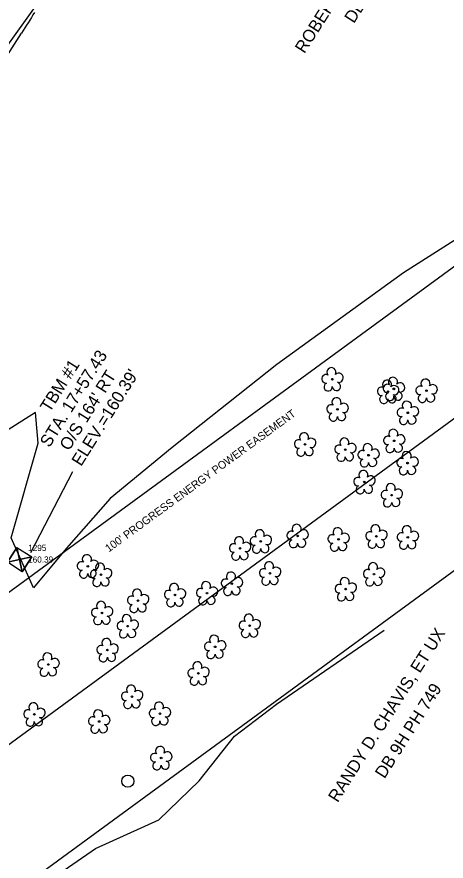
# Model space of a CAD drawing. Extents: x 1840200 to 1849051, y 348278 to 353012.
# Drawn here: x 1844872.5 to 1845047.4, y 350604.9 to 350948.7 of the extents above; entities that cross this region are included whole.
import ezdxf

# ---------------------------------------------------------------- set-up
doc = ezdxf.new("R2010")
doc.units = 0
for name, color, linetype in [('CTL Bench Mark CELL', 7, 'Continuous'), ('CTL Bench Mark Cogo Elevation', 7, 'Continuous'), ('CTL Bench Mark Cogo Number', 7, 'Continuous'), ('CTL Bench Mark Leader', 7, 'Continuous'), ('CTL Bench Mark Text', 7, 'Continuous'), ('Default', 7, 'Continuous'), ('Exist Property Deed Book Text', 7, 'Continuous'), ('Exist Property Line', 7, 'Continuous'), ('Exist Property Owner Text', 7, 'Continuous'), ('Exist Right of Way Easement Line', 7, 'Continuous'), ('Exist Right of Way Easement Line Text', 7, 'Continuous'), ('Exist Right of Way Line', 7, 'Continuous'), ('Exist Utilities Other Pole CELL', 7, 'Continuous'), ('Exist Vegetation Tree CELL', 7, 'Continuous'), ('Exist Vegetation Woods Line', 7, 'Continuous')]:
    doc.layers.add(name, color=color, linetype=linetype)

# ---------------------------------------------------------------- blocks, each defined once
blk = doc.blocks.new('CTL BENCH MARK')
at = {"layer": 'CTL Bench Mark CELL'}
blk.add_line((0, 0), (0, 0), dxfattribs=at)
blk.add_lwpolyline([(-0.072, 0.07175), (0.07175, 0.07175), (0.07175, -0.072), (-0.072, -0.072)], close=True, dxfattribs=at)
for points in [[(0.07175, 0.07175), (-0.072, -0.072), (-0.000125, -0.000125), (0.07175, -0.072), (-0.072, 0.07175)], [(-0.000125, -0.000125), (0.07175, 0.07175), (-0.072, 0.07175), (-0.000125, -0.000125)], [(-0.000125, -0.000125), (-0.072, -0.072), (0.07175, -0.072), (-0.000125, -0.000125)]]:
    blk.add_lwpolyline(points, dxfattribs=at)
blk = doc.blocks.new('EXIST UTILITIES OTHER POLE')
at = {"layer": 'Exist Utilities Other Pole CELL'}
blk.add_circle((0, 0), 0.0493, dxfattribs=at)
blk = doc.blocks.new('EXIST VEGETATION TREE')
at = {"layer": 'Exist Vegetation Tree CELL'}
blk.add_line((0, 0), (0, 0), dxfattribs=at)
blk.add_circle((0, 0), 0.00652, dxfattribs=at)
for centre, radius, start, end in [((-0.0077, 0.0575), 0.0371, 330.16508, 219.71335), ((-0.0521, 0.0031), 0.0345, 62.66361, 279.3457), ((0.051, 0.0118), 0.038, 257.1011, 134.19993), ((-0.0341, -0.0624), 0.0338, 111.56708, 6.23104), ((0.0335, -0.058), 0.034, 181.28216, 74.55999)]:
    blk.add_arc(centre, radius, start, end, dxfattribs=at)

msp = doc.modelspace()

# ---------------------------------------------------------------- linework, layer by layer
at = {"layer": 'CTL Bench Mark Leader'}
msp.add_lwpolyline([(1844878.28, 350730.61), (1844895.39, 350763.57)], dxfattribs=at)
at = {"layer": 'Exist Property Line'}
msp.add_line((1844729.25, 350550.14), (1845268.47, 350944.43), dxfattribs=at)
at = {"layer": 'Exist Right of Way Easement Line'}
for p, q in [((1844606.92, 350522.63), (1845238.95, 350984.79)), ((1844458.92, 350290.53), (1845297.98, 350904.07))]:
    msp.add_line(p, q, dxfattribs=at)
at = {"layer": 'Exist Right of Way Line'}
msp.add_line((1844461.07, 350293.9), (1844874.4, 350942.13), dxfattribs=at)
msp.add_arc((1849048.13, 348280.84), 4950, 147.36144, 147.47735, dxfattribs=at)
at = {"layer": 'Exist Vegetation Woods Line'}
for points in [[(1844796.9, 350805.6), (1844816.79, 350855.86), (1844851.04, 350912.56), (1844897.15, 350976.91), (1844931.29, 351031.99), (1844954.04, 351069.23), (1844985.12, 351120.08), (1845035.99, 351203.55)], [(1845070.01, 350869.81), (1845030.11, 350844.53), (1844978.5, 350807.17), (1844935.82, 350773.29), (1844910.5, 350752.55), (1844892.75, 350732.3), (1844879.25, 350716.15), (1844870.18, 350736.58), (1844881.18, 350775.09), (1844880.17, 350787.58), (1844859.57, 350774.67), (1844839.4, 350706.41), (1844822.64, 350670.45), (1844807.74, 350646.85), (1844790.3, 350647.95), (1844792.72, 350669.3), (1844820.73, 350703.89), (1844816.98, 350750.84), (1844800.41, 350764.51), (1844788.23, 350770.16), (1844784.85, 350775.08), (1844788.4, 350786.96), (1844796.9, 350805.6)], [(1844820.52, 350547.53), (1844856.07, 350576.6), (1844904.56, 350610.06), (1844930.4, 350621.75), (1844946.86, 350637.64), (1844961.25, 350655.71), (1844978.34, 350668.76), (1845022.23, 350698.9)]]:
    msp.add_lwpolyline(points, dxfattribs=at)

# ---------------------------------------------------------------- block references
at = {"layer": 'CTL Bench Mark CELL', "xscale": 49.99999999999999, "yscale": 50, "rotation": 57.56724915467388}
msp.add_blockref('CTL BENCH MARK', (1844873.63, 350727.7), dxfattribs=at)
at = {"layer": 'Default', "xscale": 50, "yscale": 50}
for name, p in [('EXIST VEGETATION TREE', (1845001.08, 350801.15)), ('EXIST VEGETATION TREE', (1845023.74, 350796.09)), ('EXIST VEGETATION TREE', (1845026.14, 350797.21)), ('EXIST VEGETATION TREE', (1845039.43, 350796.45)), ('EXIST VEGETATION TREE', (1845003.16, 350788.87)), ('EXIST VEGETATION TREE', (1845031.83, 350787.48)), ('EXIST VEGETATION TREE', (1845026.29, 350776.05)), ('EXIST VEGETATION TREE', (1844989.94, 350774.62)), ('EXIST VEGETATION TREE', (1845006.36, 350772.5)), ('EXIST VEGETATION TREE', (1845015.83, 350770.2)), ('EXIST VEGETATION TREE', (1845031.72, 350766.98)), ('EXIST VEGETATION TREE', (1845014.11, 350759.31)), ('EXIST VEGETATION TREE', (1845025.28, 350753.94)), ('EXIST VEGETATION TREE', (1844986.91, 350737.34)), ('EXIST VEGETATION TREE', (1844971.9, 350735.1)), ('EXIST VEGETATION TREE', (1845003.6, 350735.95)), ('EXIST VEGETATION TREE', (1845019.01, 350737.16)), ('EXIST VEGETATION TREE', (1845031.81, 350736.72)), ('EXIST VEGETATION TREE', (1844963.44, 350732.24)), ('EXIST VEGETATION TREE', (1844901.45, 350724.94)), ('EXIST VEGETATION TREE', (1844906.82, 350721.53)), ('EXIST VEGETATION TREE', (1844975.67, 350722.1)), ('EXIST VEGETATION TREE', (1845018.02, 350721.74)), ('EXIST VEGETATION TREE', (1844960.13, 350717.9)), ('EXIST VEGETATION TREE', (1844936.94, 350713.27)), ('EXIST VEGETATION TREE', (1844950, 350714.02)), ('EXIST VEGETATION TREE', (1845006.51, 350715.66)), ('EXIST VEGETATION TREE', (1844921.91, 350710.96)), ('EXIST VEGETATION TREE', (1844907.22, 350705.97)), ('EXIST VEGETATION TREE', (1844917.69, 350700.57)), ('EXIST VEGETATION TREE', (1844967.38, 350700.74)), ('EXIST VEGETATION TREE', (1844909.43, 350690.84)), ('EXIST VEGETATION TREE', (1844953.31, 350692.16)), ('EXIST VEGETATION TREE', (1844885.4, 350684.97)), ('EXIST VEGETATION TREE', (1844946.51, 350681.34)), ('EXIST VEGETATION TREE', (1844919.44, 350671.85)), ('EXIST VEGETATION TREE', (1844879.67, 350664.64)), ('EXIST VEGETATION TREE', (1844906.06, 350661.75)), ('EXIST VEGETATION TREE', (1844930.82, 350664.92)), ('EXIST VEGETATION TREE', (1844931.31, 350646.9)), ('EXIST UTILITIES OTHER POLE', (1844917.75, 350637.45))]:
    msp.add_blockref(name, p, dxfattribs=at)

# ---------------------------------------------------------------- texts
at = {"layer": 'CTL Bench Mark Cogo Elevation'}
msp.add_text('160.39', height=2.5, dxfattribs=at).set_placement((1844877.13, 350726.45))
at = {"layer": 'CTL Bench Mark Cogo Number'}
msp.add_text('1295', height=2.5, dxfattribs=at).set_placement((1844877.13, 350731.2))
at = {"layer": 'CTL Bench Mark Text'}
for s, p in [('STA. 17+57.43', (1844885.8, 350773.03)), ('TBM #1', (1844885.91, 350787.33)), ("O/S 164' RT", (1844893.8, 350771.69)), ("ELEV.=160.39'", (1844898.72, 350765.4))]:
    msp.add_text(s, height=5, rotation=57.9144, dxfattribs=at).set_placement(p)
at = {"layer": 'Exist Property Deed Book Text'}
for s, rotation, p in [('DB 9H PG 225', 57.3301, (1845009.84, 350945.79)), ('DB 9H PH 749', 57.5703, (1845022.32, 350638.19))]:
    msp.add_text(s, height=5, rotation=rotation, dxfattribs=at).set_placement(p)
at = {"layer": 'Exist Property Owner Text'}
for s, rotation, p in [('ROBERT C. COOPER, ET UX', 57.3301, (1844989.7, 350933.51)), ('RANDY D. CHAVIS, ET UX', 57.5703, (1845003.25, 350628.46))]:
    msp.add_text(s, height=5, rotation=rotation, dxfattribs=at).set_placement(p)
at = {"layer": 'Exist Right of Way Easement Line Text'}
msp.add_text("100' PROGRESS ENERGY POWER EASEMENT", height=3.2, rotation=36.175, dxfattribs=at).set_placement((1844909.97, 350730.54))

doc.saveas('drawing.dxf')
